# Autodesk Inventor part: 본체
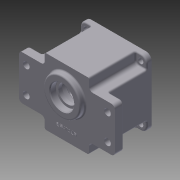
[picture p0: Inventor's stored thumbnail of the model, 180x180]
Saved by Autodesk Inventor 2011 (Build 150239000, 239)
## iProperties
Created: 2014-12
Part Number: 본체
Material: 알루미늄-6061
Document SubType Name: Modeling
Designer: Administrator
Mass: 701.457 g
Surface Area: 675.132 cm^2
Volume: 258.84 cm^3
Density: 2.71 g/cm^3
Author: Administrator
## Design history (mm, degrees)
sketch "스케치1"
  geometry: L1 (45, 45)-(-45, 45); L2 (-45, 45)-(-45, -45); L3 (-45, -45)-(45, -45); L4 (45, -45)-(45, 45); 3 further points
  constraints: 8 end point, 2 midpoint, 2 parallel, 1 horizontal, 1 horizontal alignment, 1 perpendicular, 1 vertical alignment
  dimensions: "d0" = 90 distance of L1.start L1.end; "d1" = 90 distance of L3.end L1.start
extrude "돌출1" new body sketch "스케치1" distance "d2" = 70; taper "d3" = 0 deg
sketch "스케치2"
  geometry: L1 (-65, 30)-(65, 30); L2 (65, 30)-(65, -30); L3 (65, -30)-(-65, -30); L4 (-65, -30)-(-65, 30); 3 further points
  constraints: 8 end point, 2 midpoint, 2 parallel, 1 horizontal, 1 horizontal alignment, 1 perpendicular, 1 vertical alignment
  dimensions: "d4" = 60 distance of L3.end L1.start; "d5" = 130 distance of L1.start L1.end
extrude "돌출2" join sketch "스케치2" distance "d6" = 12; taper "d7" = 0 deg
sketch "스케치3"
  geometry: C1 r 40 at (0, 0); 1 further point
  constraints: 1 centre point, 1 coincident
  dimensions: "d8" = 80 diameter of C1
extrude "돌출3" cut sketch "스케치3" distance "d9" = 9; taper "d10" = 0 deg
hole "Hole1" diameter "d13" = 78; stored, may be unused: countersink angle "d17" = 90 deg, drill point angle "d19" = 0 deg; dims "d11" = 10, "d12" = 10, "d14" = 6, "d15" = 4, "d16" = 2, "d18" = 52
sketch "스케치4"
  geometry: C1 r 25 at (0, 11); 1 further point
  constraints: 1 centre point, 1 vertical alignment
  dimensions: "d20" = 50 diameter of C1; "d21" = 11 distance of C1.centre point (0, 0)
extrude "돌출4" join sketch "스케치4" distance "d22" = 7; taper "d23" = 0 deg
sketch "스케치5"
  geometry: C1 r 39 at (0, 0) reference; C2 r 20.5 at (0, -11); C3 r 14 at (0, 20)
  constraints: 2 centre point, 2 vertical alignment
  dimensions: "d24" = 41 diameter of C2; "d25" = 28 diameter of C3; "d26" = 11 distance of C2.centre C1.centre; "d27" = 20 distance of C1.centre C3.centre
extrude "돌출5" join sketch "스케치5" distance "d28" = 7; taper "d29" = 0 deg
sketch "스케치6"
  geometry: L1 (0, 0)-(24.749, 24.749); L2 (0, 0)-(35, 0); C1 r 39 at (0, 0) reference; A1 r 35 centre (0, 0) between (24.749, 24.749) and (21.762, 27.412); A2 r 4 centre (24.749, 24.749) between (21.809, 27.462) and (27.462, 21.809); A3 r 39 centre (0, 0) between (32.777, 21.134) and (21.134, 32.777); A4 r 3.5 centre (29.836, 19.238) between (32.777, 21.134) and (27.412, 21.762); A5 r 3.5 centre (19.238, 29.836) between (21.762, 27.412) and (21.134, 32.777)
  constraints: 13 point on circle, 5 centre point, 4 end point, 4 tangent, 3 coincident, 1 equal length, 1 horizontal
  dimensions: "d75" = 70 diameter of A1; "d76" = 45 deg angle of L2 L1; "d77" = 8 diameter of A2; "d78" = 7 diameter of A4; "d79" = 7 diameter of A5
extrude "돌출6" join sketch "스케치6" stored distance "d80" = 7; taper "d81" = 0 deg
sketch "스케치7"
  geometry: L1 (45, 45)-(45, 30) reference; L2 (-45, 45)-(45, 45) reference; L3 (45, 30)-(30, 30); L4 (30, 30)-(30, 45); L5 (30, 45)-(45, 45); L6 (45, 45)-(45, 30); 1 further point
  constraints: 8 end point, 2 parallel, 1 horizontal, 1 perpendicular, 1 point on line
  dimensions: "d85" = 30 distance from line of L4 point (0, 0)
extrude "돌출7" cut sketch "스케치7" distance "d86" = 63; taper "d87" = 0 deg
fillet "모깎기1" dims "d91" = 5, "d92" = 8
hole "Hole7" diameter "d95" = 7; stored, may be unused: countersink angle "d99" = 90 deg, drill point angle "d101" = 0 deg; dims "d93" = 10, "d94" = 10, "d96" = 6, "d97" = 4, "d98" = 2, "d100" = 7
hole "Hole8" diameter "d107" = 3.459; stored, may be unused: countersink angle "d111" = 90 deg, drill point angle "d113" = 118 deg; dims "d105" = 10, "d106" = 10, "d108" = 12, "d109" = 4, "d110" = 2, "d112" = 15
sketch "스케치8"
  geometry: 2 further points
  dimensions: "d117" = 55 horizontal distance of point (0, 0) point (-55, 17.5); "d118" = 17.5 vertical distance of point (-55, 17.5) point (0, 0)
hole "Hole9" sketch "스케치8" at (-55, 17.5) diameter "d119" = 9; stored, may be unused: countersink angle "d123" = 90 deg, drill point angle "d125" = 0 deg; dims "d120" = 12, "d121" = 4, "d122" = 2, "d124" = 12
sketch "스케치11"
  geometry: C1 r 17.5 at (0, -11); A1 r 20.5 centre (0, -11) between (-7.402, 8.117) and (7.402, 8.117) reference; 1 further point
  constraints: 1 centre point, 1 coincident
  dimensions: "d144" = 35 diameter of C1
extrude "돌출9" cut sketch "스케치11" distance "d145" = 10; taper "d146" = 0 deg
sketch "스케치12"
  geometry: C1 r 17.5 at (0, 0) reference; C2 r 12.5 at (0, 0); 1 further point
  constraints: 1 centre point, 1 coincident
  dimensions: "d147" = 25 diameter of C2
extrude "돌출10" cut sketch "스케치12" distance "d148" = 5; taper "d149" = 0 deg
sketch "스케치13"
  geometry: C1 r 25 at (0, 0) reference; C2 r 16 at (0, 0); 1 further point
  constraints: 1 centre point, 1 coincident
  dimensions: "d150" = 32 diameter of C2
extrude "돌출11" cut sketch "스케치13" distance "d151" = 8; taper "d152" = 0 deg
sketch "스케치14"
  geometry: C1 r 11 at (0, 20); A1 r 14 centre (0, 20) between (7.402, 8.117) and (-7.402, 8.117) reference; 1 further point
  constraints: 1 centre point, 1 coincident
  dimensions: "d153" = 22 diameter of C1
extrude "돌출12" cut sketch "스케치14" distance "d154" = 7; taper "d155" = 0 deg
sketch "스케치15"
  geometry: C1 r 11 at (0, 0) reference; C2 r 9.5 at (0, 0); 1 further point
  constraints: 1 centre point, 1 coincident
  dimensions: "d156" = 19 diameter of C2
extrude "돌출13" cut sketch "스케치15" distance "d157" = 1; taper "d158" = 0 deg
sketch "스케치17"
  geometry: A1 r 20.5 centre (0, -11) between (-7.402, 8.117) and (7.402, 8.117) reference; A2 r 14 centre (0, 20) between (7.402, 8.117) and (-7.402, 8.117) reference; A3 r 3 centre (12.742, 8.746) between (10.493, 10.732) and (11.115, 6.225); A4 r 3 centre (-12.742, 8.746) between (-11.115, 6.225) and (-10.493, 10.732); A5 r 14 centre (0, 20) between (-10.493, 10.732) and (-7.402, 8.117); A6 r 20.5 centre (0, -11) between (-7.402, 8.117) and (-11.115, 6.225); A7 r 14 centre (0, 20) between (7.402, 8.117) and (10.493, 10.732); A8 r 20.5 centre (0, -11) between (11.115, 6.225) and (7.402, 8.117)
  constraints: 16 point on circle, 6 centre point, 4 concentric, 4 tangent
  dimensions: "d167" = 6 diameter of A3; "d168" = 6 diameter of A4
extrude "돌출15" join sketch "스케치17" stored distance "d169" = 1; taper "d170" = 0 deg
chamfer "모따기2" distance "d159" = 1; stored, may be unused: second distance "d160" = 2, angle "d161" = 45 deg
fillet "모깎기4" dims "d171" = 2, "d172" = 0.3
sketch "스케치18"
  geometry: L1 (28, -45)-(-28, -45) reference; 2 further points
  constraints: 1 vertical alignment, 1 other
  dimensions: "d173" = 15 distance from line of point (0, -30) L1
feature "엠보싱2" sketch "스케치18" dims "d0" = 90, "d1" = 90, "d174" = 0.5, "d175" = 0
fillet "모깎기5" dims "d176" = 5
node "솔리드1"
pattern_circular "원형 패턴1" dims angle "d83" = 360 deg
pattern_circular "원형 패턴2" dims angle "d89" = 360 deg
pattern_circular "원형 패턴3" dims angle "d103" = 360 deg
pattern_circular "원형 패턴4" dims angle "d115" = 360 deg
pattern_linear "직사각형 패턴1" dims "d128" = 110, "d131" = 35
